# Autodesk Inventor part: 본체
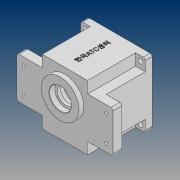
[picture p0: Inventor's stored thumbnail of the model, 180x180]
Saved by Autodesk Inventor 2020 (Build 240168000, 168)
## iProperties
Created: 2020-07
Part Number: 본체
Material: 일반
Document SubType Name: Modeling
Designer: PC312-
Density: 1 g/cm^3
Appearance: 기본값
Mass: 324.627 g
Surface Area: 794.194 cm^2
Volume: 324.627 cm^3
Author: PC312-
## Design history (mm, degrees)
sketch "스케치1"
  geometry: L1 (-47, 47)-(47, 47); L2 (47, 47)-(47, -47); L3 (47, -47)-(-47, -47); L4 (-47, -47)-(-47, 47); L5 (-47, 47)-(47, -47); L6 (47, 47)-(-47, -47); 1 further point
  constraints: 12 end point, 2 midpoint, 2 parallel, 1 horizontal, 1 perpendicular
  dimensions: "d0" = 94 distance of L2.end L3.end; "d1" = 94 distance of L1.end L2.end
extrude "돌출1" new body sketch "스케치1" distance "d2" = 10; taper "d3" = 0 deg
sketch "스케치2"
  geometry: L1 (-33, 47)-(33, 47); L2 (33, 47)-(33, -47); L3 (33, -47)-(-33, -47); L4 (-33, -47)-(-33, 47); L5 (47, 47)-(-47, 47) reference; L6 (-47, -47)-(47, -47) reference; L7 (-47, 47)-(-47, -47) reference; L8 (-47, 30)-(47, 30); L9 (47, 30)-(47, -30); L10 (47, -30)-(-47, -30); L11 (-47, -30)-(-47, 30); L12 (47, -47)-(47, 47) reference; 8 further points
  constraints: 16 end point, 4 parallel, 3 collinear, 2 horizontal, 2 midpoint, 2 perpendicular, 1 horizontal alignment, 1 point on line, 1 vertical alignment
  dimensions: "d4" = 66 distance of L2.end L3.end; "d5" = 60 distance of L8.end L9.end
extrude "돌출2" join sketch "스케치2" distance "d6" = 70; taper "d7" = 0 deg
sketch "스케치3"
  geometry: L1 (-70, 30)-(70, 30); L2 (70, 30)-(70, -30); L3 (70, -30)-(-70, -30); L4 (-70, -30)-(-70, 30); 3 further points
  constraints: 8 end point, 2 midpoint, 2 parallel, 1 horizontal, 1 horizontal alignment, 1 perpendicular, 1 vertical alignment
  dimensions: "d8" = 140 distance between parallel lines of L2 L4; "d9" = 60 distance between parallel lines of L3 L1
extrude "돌출3" join sketch "스케치3" distance "d10" = 13; taper "d11" = 0 deg
sketch "스케치4"
  geometry: C1 r 43 at (0, 0); 1 further point
  constraints: 1 centre point, 1 coincident
  dimensions: "d12" = 86 diameter of C1
extrude "돌출4" cut sketch "스케치4" distance "d13" = 9; taper "d14" = 0 deg
sketch "스케치5"
  geometry: C1 r 40 at (0, 0); 1 further point
  constraints: 1 centre point, 1 coincident
  dimensions: "d15" = 80 diameter of C1
sketch "스케치6"
  geometry: C1 r 27.5 at (0, 11); 1 further point
  constraints: 1 centre point, 1 vertical alignment
  dimensions: "d16" = 55 diameter of C1; "d17" = 11 distance of point (0, 0) C1.centre
extrude "돌출5" join sketch "스케치6" distance "d18" = 7; taper "d19" = 0 deg
extrude "돌출6" cut sketch "스케치5" distance "d20" = 62; taper "d21" = 0 deg
sketch "스케치8"
  geometry: C1 r 27.5 at (0, 0) reference; C2 r 16 at (0, 0); 1 further point
  constraints: 1 centre point, 1 coincident
  dimensions: "d22" = 32 diameter of C2
extrude "돌출7" cut sketch "스케치8" distance "d23" = 8.3; taper "d24" = 0 deg
node "작업 평면1"
sketch "스케치12"
  geometry: C1 r 16 at (0, 0) reference; C2 r 17.5 at (0, 0); 1 further point
  constraints: 1 centre point, 1 coincident
  dimensions: "d32" = 35 diameter of C2
extrude "돌출10" join sketch "스케치12" stored distance "d33" = 4.7; taper "d34" = 0 deg
sketch "스케치13"
  geometry: C1 r 16 at (0, 0) reference; C2 r 12.5 at (0, 0); 1 further point
  constraints: 1 centre point, 1 coincident
  dimensions: "d35" = 25 diameter of C2
extrude "돌출11" cut sketch "스케치13" distance "d36" = 4.7; taper "d37" = 0 deg
sketch "스케치16"
  geometry: C1 r 17.5 at (0, 0) reference; C2 r 21 at (0, 0); 1 further point
  constraints: 1 centre point, 1 coincident
  dimensions: "d39" = 42 diameter of C2
extrude "돌출12" join sketch "스케치16" stored distance "d40" = 4.7; taper "d41" = 0 deg
sketch "스케치17"
  geometry: C1 r 21 at (0, 0) reference; C2 r 17.5 at (0, 0); 1 further point
  constraints: 1 centre point, 1 coincident
  dimensions: "d42" = 35 diameter of C2
extrude "돌출13" cut sketch "스케치17" distance "d43" = 10; taper "d44" = 0 deg
sketch "스케치19"
  geometry: C1 r 15 at (0, -31); 1 further point
  constraints: 1 centre point, 1 vertical alignment
  dimensions: "d47" = 30 diameter of C1; "d48" = 20 distance of point (0, -11) C1.centre
extrude "돌출14" join sketch "스케치19" stored distance "d49" = 10; taper "d50" = 0 deg
sketch "스케치20"
  geometry: C1 r 11 at (0, -31); A1 r 15 centre (0, -31) between (-8.978, -18.984) and (8.978, -18.984) reference; 1 further point
  constraints: 1 centre point, 1 coincident
  dimensions: "d51" = 22 diameter of C1
extrude "돌출15" cut sketch "스케치20" distance "d52" = 7; taper "d53" = 0 deg
sketch "스케치21"
  geometry: C1 r 12.5 at (0, 0) reference; C2 r 17.5 at (0, 0); 1 further point
  constraints: 1 centre point, 1 coincident
  dimensions: "d54" = 35 diameter of C2
extrude "돌출16" cut sketch "스케치21" distance "d55" = 10; taper "d56" = 0 deg
sketch "스케치22"
  geometry: C1 r 11 at (0, 0) reference; C2 r 9.5 at (0, 0); 1 further point
  constraints: 1 centre point, 1 coincident
  dimensions: "d57" = 19 diameter of C2
extrude "돌출17" cut sketch "스케치22" distance "d58" = 3; taper "d59" = 0 deg
sketch "스케치23"
  geometry: A1 r 36 centre (0, 0) between (36, 0) and (35.772, 4.045); A2 r 4 centre (36, 0) between (36.19, 3.995) and (36.19, -3.995); A3 r 3 centre (36.333, 6.992) between (35.772, 4.045) and (39.279, 7.559); A4 r 40 centre (0, 0) between (39.279, 7.559) and (39.279, -7.559) reference; A5 r 3 centre (36.333, -6.992) between (39.279, -7.559) and (35.772, -4.045); 1 further point
  constraints: 13 point on circle, 4 centre point, 4 tangent, 1 coincident, 1 horizontal alignment
  dimensions: "d60" = 72 diameter of A1; "d61" = 8 diameter of A2; "d62" = 6 diameter of A3; "d63" = 6 diameter of A5
extrude "돌출18" join sketch "스케치23" stored distance "d64" = 3; taper "d65" = 0 deg
fillet "모깎기1" dims "d66" = 3
fillet "모깎기2" dims "d67" = 3
sketch "스케치26"
  geometry: C1 r 2.25 at (60, 19); 1 further point
  constraints: 1 centre point
  dimensions: "d70" = 4.5 diameter of C1; "d71" = 60 horizontal distance of C1.centre point (0, 0); "d72" = 19 vertical distance of C1.centre point (0, 0)
extrude "돌출19" cut sketch "스케치26" distance "d73" = 8; taper "d74" = 0 deg
sketch "스케치27"
  geometry: C1 r 2.25 at (-60, 19) reference; C2 r 5 at (-60, 19); 1 further point
  constraints: 1 centre point, 1 coincident
  dimensions: "d75" = 10 diameter of C2
extrude "돌출20" cut sketch "스케치27" distance "d76" = 5; taper "d77" = 0 deg
sketch "스케치28"
  geometry: C1 r 3.5 at (40, 40); 1 further point
  constraints: 1 centre point
  dimensions: "d84" = 7 diameter of C1; "d85" = 40 horizontal distance of C1.centre point (0, 0); "d86" = 40 horizontal distance of C1.centre point (0, 0)
extrude "돌출21" cut sketch "스케치28" extent not by distance; stored distance "d87" = 5; taper "d88" = 0 deg
node "작업 평면3"
sketch "스케치30"
  geometry: L1 (77, 80)-(-11, 80) reference; 3 further points
  constraints: 1 midpoint, 1 vertical alignment, 1 other
  dimensions: "d96" = 40 distance from line of L1 point (33, 40)
feature "엠보싱1" sketch "스케치30" dims "d5" = 60, "d97" = 0.5, "d98" = 0
chamfer "모따기2" distance "d102" = 1; stored, may be unused: second distance "d103" = 2, angle "d104" = 45 deg
chamfer "모따기3" distance "d105" = 0.8; stored, may be unused: second distance "d106" = 2, angle "d107" = 30 deg
fillet "모깎기3" dims "d108" = 1
fillet "모깎기4" dims "d109" = 1
fillet "모깎기5" dims "d110" = 3
sketch "스케치31"
  geometry: A1 r 4 centre (-36, 0) between (-36.19, -3.995) and (-36.19, 3.995) reference; A2 r 4 centre (36, 0) between (36.19, 3.995) and (36.19, -3.995) reference; 3 further points
  constraints: 2 coincident
hole "구멍1" sketch "스케치31" at (-36, 0), (36, 0) diameter "d111" = 3.242; stored, may be unused: countersink angle "d115" = 90 deg, drill point angle "d117" = 118 deg; dims "d112" = 7, "d113" = 4, "d114" = 2, "d116" = 9
node "솔리드1"
mirror "미러1"
pattern_linear "직사각형 패턴1" dims "d80" = 120
pattern_linear "직사각형 패턴2" dims "d83" = 38
pattern_linear "직사각형 패턴3" dims "d91" = 80
pattern_linear "직사각형 패턴4" dims "d94" = 80
node "작업 평면2"
feature "A9D066F2-1C7D-4E18-AEED-F7BC21143FA4" dims "d111" = 3.242, "d112" = 7, "d113" = 4, "d114" = 2, "d115" = 90 deg, "d116" = 9, "d117" = 118 deg
other parameters: "d28" = -23
